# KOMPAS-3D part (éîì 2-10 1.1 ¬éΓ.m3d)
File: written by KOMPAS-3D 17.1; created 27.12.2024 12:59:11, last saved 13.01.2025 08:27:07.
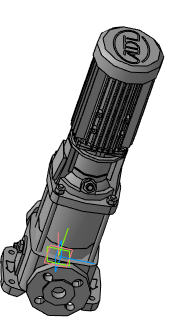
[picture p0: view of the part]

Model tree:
1. Операция без истории:4  (labels: ВМН 2-10 1.1 кВт)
